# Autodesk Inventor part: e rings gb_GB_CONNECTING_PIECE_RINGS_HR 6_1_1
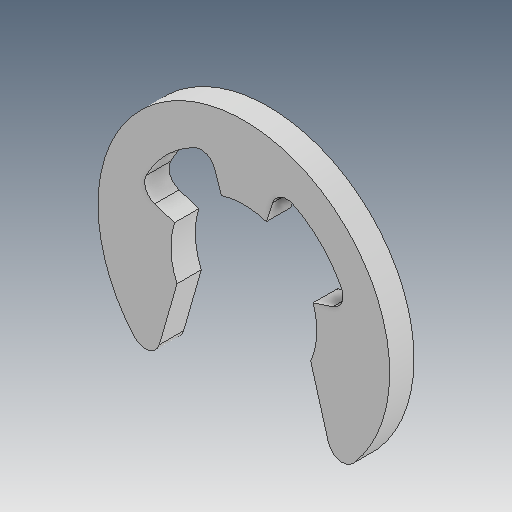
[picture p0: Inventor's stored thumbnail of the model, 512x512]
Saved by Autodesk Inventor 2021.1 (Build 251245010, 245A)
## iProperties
Created: 2019-04
Part Number: e rings gb_GB_CONNECTING_PIECE_RINGS_HR 6_1_1
Material: Ogólny
Document SubType Name: Modeling
Designer: user
Density: 1 g/cm^3
Appearance: Domyślna
Author: user
Revision Number: ÈÎºÎ
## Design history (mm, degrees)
feature "ÊäÈë1"
node "Bryła1"
